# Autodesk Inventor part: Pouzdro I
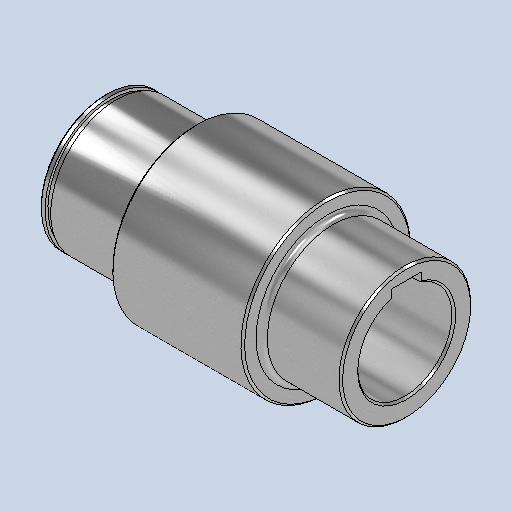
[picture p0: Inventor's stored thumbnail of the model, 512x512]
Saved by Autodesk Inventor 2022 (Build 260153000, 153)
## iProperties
Created: 2025-05
Part Number: Pouzdro I
Material: Všeobecné
Document SubType Name: Modeling
Designer: jbart
Density: 1 g/cm^3
Appearance: Broušená
Mass: 437.398 g
Surface Area: 779.013 cm^2
Volume: 437.398 cm^3
Author: jbart
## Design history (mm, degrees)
sketch "Náčrt1"
  geometry: L1 (0, 0)-(160, 0); L2 (0, 23)-(50, 23); L3 (50, 23)-(50, 30); L4 (50, 30)-(100, 30); L5 (100, 30)-(100, 25); L6 (100, 25)-(160, 25); L7 (0, 23)-(0, 35); L8 (48, 35)-(48, 45); L9 (48, 45)-(118, 45); L10 (118, 45)-(118, 35); L11 (160, 35)-(160, 25); L12 (3, 35)-(3, 33.5); L13 (3, 33.5)-(6, 33.5); L14 (6, 33.5)-(6, 35); L15 (0, 35)-(3, 35); L16 (6, 35)-(48, 35); L17 (118, 35)-(160, 35); 3 further points
  constraints: 34 end point, 11 perpendicular, 3 vertical, 2 horizontal, 2 horizontal alignment, 2 midpoint, 2 vertical alignment, 1 parallel, 1 point on line
  dimensions: "d0" = 160 distance of L1.start L1.end; "d1" = 50 distance of L2.start L2.end; "d2" = 60 distance of L5.end L6.end; "d3" = 46 diameter of L2 L1; "d4" = 50 diameter of L6 L1; "d5" = 60 diameter of L4 L1; "d7" = 48 distance of L7.end L8.start; "d9" = 90 diameter of L9 L1; "d33" = 3 distance of L12.end L13.end; "d34" = 42 distance between parallel lines of L8 L14; "d35" = 70 diameter of L16 L1; "d36" = 67 diameter of L13 L1; "d37" = 42 distance of L10.end L11.start
revolve "Rotace1" sketch "Náčrt1" stored, may be unused: angle "d10" = 90 deg
sketch "Náčrt2"
  geometry: L1 (-8, 23.685)-(-8, 28.8); L2 (-8, 28.8)-(8, 28.8); L3 (8, 28.8)-(8, 23.685); A1 r 25 centre (0, 0) between (-8, 23.685) and (8, 23.685) reference; 2 further points
  constraints: 6 end point, 2 perpendicular, 2 point on circle, 1 midpoint, 1 vertical, 1 vertical alignment
  dimensions: "d11" = 16 distance of L1.end L2.end; "d12" = 28.8 distance from line of L2 point (0, 0)
extrude "Vysunutí1" cut sketch "Náčrt2" distance "d13" = 60; taper "d14" = 0 deg
fillet "Zaoblení1" dims "d15" = 0.6
sketch "Náčrt3"
  geometry: L1 (-4.5, 24.592)-(-4.5, 22.555); L2 (4.5, 24.592)-(4.5, 22.555); L3 (0, 0)-(0, 5); A1 r 23 centre (0, 0) between (4.5, 22.555) and (-4.5, 22.555) reference; A2 r 25 centre (0, 0) between (4.5, 24.592) and (-4.5, 24.592); 1 further point
  constraints: 6 end point, 4 point on circle, 3 vertical, 1 centre point, 1 coincident, 1 other
  dimensions: "d20" = 50 diameter of A2; "d21" = 9 distance between parallel lines of L1 L2; "d22" = 5 distance of L3.start L3.end
extrude "Vysunutí2" cut sketch "Náčrt3" distance "d18" = 50; taper "d19" = 0 deg
pattern_circular "Kruhové pole1" dims angle "d24" = 360 deg
chamfer "Zkosení2" distance "d29" = 1; stored, may be unused: second distance "d30" = 2, angle "d31" = 45 deg
fillet "Zaoblení2" dims "d32" = 3
chamfer "Zkosení3" distance "d38" = 1; stored, may be unused: second distance "d39" = 2, angle "d40" = 45 deg
chamfer "Zkosení4" distance "d41" = 1; stored, may be unused: second distance "d42" = 2, angle "d43" = 45 deg
node "Těleso1"
